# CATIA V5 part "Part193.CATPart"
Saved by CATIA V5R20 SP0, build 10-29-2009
Part number: FA 168700-1
Revision: ANY
Definition: UNKNOWN
Nomenclature: FA 168700-1
Source: Unknown
Bounding box of the stored display mesh (mm): x -3.804 to 3.804, y 0.28 to 2.5, z -4 to 4
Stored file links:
  C:\Users\Utente\Desktop\IO LAVORO\3D X SITO CF\CUMSA\3D files FA\FA 168700\Part193.CATPart
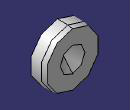
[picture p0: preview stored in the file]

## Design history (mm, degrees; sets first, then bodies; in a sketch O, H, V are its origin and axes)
Body1 "Cortar-Extruir1" (main body)
  Solid1: solid without history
